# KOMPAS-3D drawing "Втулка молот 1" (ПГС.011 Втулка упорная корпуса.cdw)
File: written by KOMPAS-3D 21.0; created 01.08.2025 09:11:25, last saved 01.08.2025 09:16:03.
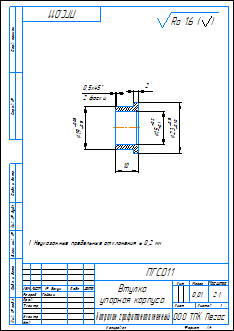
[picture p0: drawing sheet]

Sheet 1: A4, portrait

Document properties: Полное имя файла: ..\Модель\ПГС.011 Втулка упорная корпуса.m3d; Автор: User; Знак неуказанной шероховатости: 4; Параметр неуказанной шероховатости: Ra 1.6; Масса: 0.01036

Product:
- Part/product: Втулка молот 1
    Масса: 0.01036
    Форматы листов документа: A4

Title block, sheet 1: Наименование: Втулка / упорная корпуса; designation: ПГС.011; Материал: Капролон графитонаполненный; Масса: 0,01; Количество листов документа: 1; organisation: ООО ТПК Пегас; Форматы листов документа: A4; stored path: C:\Users\User\Desktop\ПЕРСПЕКТИВА кд\Чертежи\ПГС.011 Втулка упорная корпуса.cdw; Разработал: Гайсин

Views: Вид 1, Спереди, Проекционный вид 2, Местный разрез 1
Referenced files in C:\Users\User\Desktop\ПЕРСПЕКТИВА кд\Модель\: ПГС.011 Втулка упорная корпуса.m3d
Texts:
  Втулка молот 1
  Ra 1.6
  Ra 1.6 ( )
Dimensions and other numbers on the sheet: 19; 15; 23; 2; 10; 0,5; 2 фаски; 2:1; 1; 0,01

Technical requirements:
  Неуказанные предельные отклонения   0,2 мм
